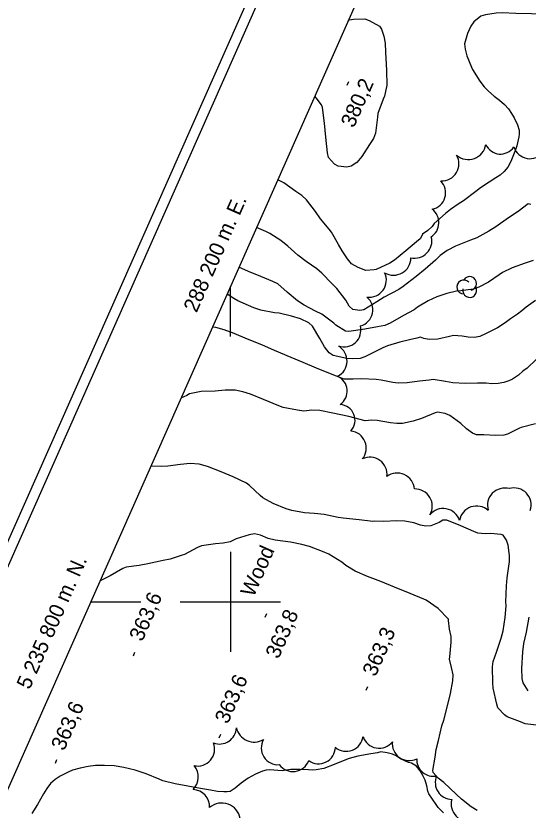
# Model space of a CAD drawing. Extents: x 287698 to 290158, y 5234163 to 5237182.
# Drawn here: x 288157.2 to 288259.4, y 5235758.4 to 5235917 of the extents above; entities that cross this region are included whole.
import ezdxf

# ---------------------------------------------------------------- set-up
doc = ezdxf.new("R2010")
doc.units = 0
for name, color, linetype in [('Niveau 1', 7, 'Continuous'), ('Niveau 2', 7, 'Continuous'), ('Niveau 3', 7, 'Continuous'), ('Niveau 44', 7, 'Continuous'), ('Niveau 60', 7, 'Continuous'), ('Niveau 61', 7, 'Continuous'), ('Niveau 7', 7, 'Continuous')]:
    doc.layers.add(name, color=color, linetype=linetype)

msp = doc.modelspace()

# ---------------------------------------------------------------- linework, layer by layer
at = {"layer": 'Niveau 1'}
for points in [[(288223.52, 5235916.11), (288223.77, 5235916.22), (288224.59, 5235916.4), (288226.82, 5235916.47), (288227.72, 5235916.09), (288229.73, 5235914.96), (288230.18, 5235914.38), (288230.63, 5235913.01), (288230.88, 5235911.6), (288230.97, 5235909.81), (288231.16, 5235906.1)], [(288231.16, 5235906.1), (288231.23, 5235903.22), (288230.74, 5235901.02), (288230.48, 5235900.41), (288229.44, 5235897.53), (288229.36, 5235896.82), (288228.98, 5235893.58), (288228.54, 5235892.53), (288227.79, 5235891.35), (288226.2, 5235888.97), (288225.23, 5235887.76), (288224.08, 5235887.02), (288223.22, 5235886.82), (288221.5, 5235887.01), (288220.79, 5235887.4), (288219.6, 5235888.78), (288219.39, 5235889.7), (288219.08, 5235892.82), (288218.77, 5235895.64), (288218.4, 5235898.72), (288218.2, 5235899.27), (288217.12, 5235900.68), (288216.82, 5235900.98)], [(288222.7, 5235844.46), (288219.98, 5235845.53), (288217.19, 5235846.69), (288214.55, 5235847.8), (288212.14, 5235848.8), (288208.83, 5235850.19), (288206.25, 5235851.3), (288203.42, 5235852.48), (288200.78, 5235853.59), (288198.77, 5235854.3), (288197.07, 5235854.77), (288196.41, 5235854.87)], [(288261.04, 5235848.38), (288259.24, 5235846.65), (288258.36, 5235846.04), (288257.48, 5235845.29), (288256.28, 5235844.47), (288255.57, 5235844.13), (288254.58, 5235843.78), (288253.44, 5235843.59), (288252.21, 5235843.56), (288251.04, 5235843.66), (288249.29, 5235843.67), (288246.86, 5235843.63), (288244.37, 5235843.75), (288242.96, 5235844), (288240.46, 5235844.42)], [(288240.46, 5235844.42), (288239.64, 5235844.24), (288237.75, 5235844.04), (288235.27, 5235843.74), (288233.5, 5235843.67), (288232.39, 5235843.78), (288230.08, 5235844.29), (288229.07, 5235844.4), (288226.11, 5235844.52), (288224.53, 5235844.46), (288222.7, 5235844.46)]]:
    msp.add_lwpolyline(points, dxfattribs=at)
at = {"layer": 'Niveau 2'}
for points in [[(288265.93, 5235917.61), (288263.29, 5235917.22), (288260.13, 5235917.46), (288256.95, 5235917.54), (288254.25, 5235917.67), (288253.07, 5235917.61), (288250.91, 5235917.27), (288250, 5235916.96), (288248.57, 5235915.85), (288247.96, 5235914.99), (288247.31, 5235913.49), (288246.75, 5235911.43), (288246.84, 5235910.36), (288247.18, 5235909.09), (288248.1, 5235906.82), (288248.35, 5235906.34)], [(288248.35, 5235906.34), (288249.8, 5235903.99), (288250.62, 5235902.86), (288251.49, 5235901.97), (288252.62, 5235901.03), (288253.71, 5235900.21), (288254.72, 5235899.35), (288255.51, 5235898.46), (288256.13, 5235897.57), (288256.65, 5235896.67), (288257.29, 5235895.27), (288257.62, 5235894.2), (288257.66, 5235893.38), (288257.57, 5235892.85), (288257.18, 5235891.11), (288256.75, 5235889.92), (288255.99, 5235887.98), (288255.38, 5235886.82), (288254.65, 5235885.94), (288253.85, 5235885.25), (288253.01, 5235884.66), (288251.66, 5235883.83), (288249.89, 5235882.66), (288248.98, 5235881.93), (288246.55, 5235880.07), (288245.45, 5235879.4), (288243.9, 5235878.37), (288242.92, 5235877.57), (288240.7, 5235875.57), (288240.26, 5235874.98), (288239.42, 5235874.19), (288238.36, 5235873.45), (288238.23, 5235873.12)], [(288238.23, 5235873.12), (288237.87, 5235872.49), (288237.16, 5235871.91), (288235, 5235870.09), (288232.76, 5235868.23), (288231.84, 5235867.65), (288229.12, 5235866.36), (288228.71, 5235866.28), (288227.01, 5235866.15), (288225.52, 5235866.75), (288224.2, 5235867.52), (288223.36, 5235868.49), (288222.29, 5235870.09), (288221.58, 5235871.37), (288220.18, 5235873.83), (288219.71, 5235874.43), (288217.95, 5235876.52), (288216.96, 5235877.94), (288215.21, 5235880.29), (288214.27, 5235881.17), (288213.08, 5235881.98), (288210.66, 5235883.69), (288209.74, 5235884.16), (288209.43, 5235884.29)], [(288259.41, 5235879.48), (288257.45, 5235877.98), (288255.53, 5235876.73), (288252.95, 5235874.89), (288251.57, 5235874.03), (288249.18, 5235872.7), (288247.9, 5235872.24), (288244.96, 5235871.01), (288243.25, 5235870.18), (288241.87, 5235869.2), (288240.92, 5235868.26), (288238.9, 5235866.46), (288237.11, 5235865.01), (288234.45, 5235862.95), (288233.59, 5235862.4), (288230.67, 5235860.83), (288229.22, 5235859.92), (288226.64, 5235858.35), (288225.86, 5235858.18), (288224.46, 5235858.41), (288223.71, 5235859.08), (288223.02, 5235860.24), (288221.25, 5235862.55), (288220.25, 5235863.57), (288218.24, 5235865.63), (288217.23, 5235866.48), (288215.11, 5235867.96), (288213.46, 5235869.27), (288211.46, 5235871.04), (288210.06, 5235872.15), (288207.85, 5235873.57), (288207.06, 5235873.96), (288205.22, 5235874.77)], [(288259.96, 5235879.35), (288259.41, 5235879.48), (288259.41, 5235879.48)], [(288260.4, 5235868.17), (288258.83, 5235867.67), (288256.23, 5235866.74), (288254.29, 5235865.81), (288253.63, 5235865.34), (288251.53, 5235863.83), (288249.59, 5235862.83), (288248.44, 5235862.45), (288245.99, 5235862.1), (288245.15, 5235862.08), (288243.2, 5235861.61), (288241.19, 5235860.94), (288239.45, 5235860.14), (288237.36, 5235858.84), (288236.7, 5235858.31), (288234.58, 5235857.18), (288231.88, 5235855.64), (288230.84, 5235855.17), (288229.35, 5235854.95), (288226.82, 5235854.45), (288223.66, 5235853.97), (288222.99, 5235854.08), (288221.02, 5235855.26), (288220.62, 5235855.64), (288218.22, 5235857.45), (288217.01, 5235858.05), (288214.73, 5235859.23), (288213.36, 5235860.14), (288211.34, 5235861.82), (288209.46, 5235863.52), (288208.5, 5235863.95), (288206.06, 5235864.96), (288203.64, 5235866.01), (288201.69, 5235866.81)], [(288237.95, 5235852.89), (288237.19, 5235852.66), (288235.75, 5235852.33), (288233.82, 5235851.86), (288231.33, 5235851.13), (288230.41, 5235850.71), (288226.81, 5235848.95), (288225.87, 5235848.63), (288224.27, 5235848.52), (288223.25, 5235848.61), (288220.51, 5235849.2), (288219.71, 5235849.72), (288218.81, 5235850.93), (288217.84, 5235852.6), (288216.38, 5235855.08), (288215.65, 5235855.7), (288213.98, 5235856.49), (288212.21, 5235857.08), (288209.74, 5235857.64), (288208.82, 5235857.74), (288206.09, 5235858.27), (288204.69, 5235858.7), (288201.45, 5235860.11), (288200.67, 5235860.57), (288199.33, 5235861.46)], [(288260.87, 5235860.17), (288259.06, 5235858.86), (288258.2, 5235858.11), (288257.32, 5235857.48), (288255.88, 5235856.54), (288254.84, 5235855.74), (288253.33, 5235854.74), (288252.22, 5235854.22), (288251.07, 5235853.57), (288249.79, 5235853), (288248.66, 5235852.81), (288247.49, 5235852.88), (288246.26, 5235853.09), (288244.54, 5235853.19), (288243.74, 5235853), (288241.37, 5235852.49), (288239.66, 5235852.38), (288238.61, 5235852.56), (288237.95, 5235852.89)], [(288226.87, 5235836.14), (288223.62, 5235837.01), (288220.47, 5235837.65), (288217.88, 5235838.2), (288216.23, 5235838.27), (288214.65, 5235838.09), (288213.36, 5235838.25), (288210.5, 5235838.8), (288209.65, 5235839.12), (288206.6, 5235840.4), (288204.04, 5235841.47), (288202.5, 5235841.96), (288200.93, 5235842.24), (288198.96, 5235842.26), (288196.97, 5235842.1), (288194.16, 5235842), (288191.86, 5235841.56), (288191.27, 5235841.21), (288190.13, 5235840.7)], [(288260.87, 5235835.55), (288258.02, 5235834.84), (288257.67, 5235834.65), (288255.33, 5235833.51), (288254.58, 5235833.3), (288252.94, 5235833.23), (288250.61, 5235833.37), (288249.09, 5235833.32), (288248.31, 5235833.68), (288247.13, 5235834.55), (288245.99, 5235835.61), (288243.79, 5235837.22), (288242.85, 5235837.64), (288241.34, 5235837.9), (288240.87, 5235837.75), (288238.16, 5235836.62), (288236.49, 5235836.11), (288234.38, 5235835.62), (288233.19, 5235835.59), (288231.93, 5235835.77), (288229.29, 5235836.22), (288228.26, 5235836.28), (288226.87, 5235836.14)], [(288228.44, 5235816.04), (288225.69, 5235816.38), (288222.49, 5235816.68), (288221.48, 5235816.86), (288218.73, 5235817.42), (288216.77, 5235817.65), (288214.76, 5235817.75), (288212.25, 5235818.21), (288211.15, 5235818.57), (288208.56, 5235819.66), (288206.49, 5235820.74), (288205.91, 5235821.2), (288203.82, 5235823.26), (288203.2, 5235823.7), (288200.52, 5235824.94), (288198.16, 5235825.93), (288195.45, 5235827.01), (288193.74, 5235827.46), (288191.94, 5235827.63), (288190.05, 5235827.42), (288187.54, 5235827.08), (288186.22, 5235827.04), (288184.1, 5235827.06)], [(288262.19, 5235775.22), (288258.85, 5235775.64), (288257.88, 5235775.99), (288255.27, 5235777.04), (288254.72, 5235777.41), (288253.39, 5235778.84), (288253.15, 5235779.52), (288252.46, 5235782.73), (288252.38, 5235783.8), (288252.34, 5235786.98), (288252.47, 5235788.1), (288253.12, 5235789.96), (288254.07, 5235792.75), (288254.44, 5235794.22), (288254.81, 5235796.89), (288255.01, 5235799.2), (288254.96, 5235800), (288255.08, 5235803.19), (288255.25, 5235804.79), (288255.71, 5235808.02), (288255.72, 5235809.26), (288255.44, 5235811.34), (288255.1, 5235812.28), (288254.43, 5235813.31), (288254.03, 5235813.47), (288251.94, 5235813.67), (288250.88, 5235813.58), (288249.36, 5235813.72), (288248.61, 5235814.04), (288245.97, 5235815.14), (288243.22, 5235816.29), (288242.37, 5235816.27), (288241.68, 5235815.84), (288240, 5235815.15), (288238.99, 5235815.1), (288237.92, 5235815.3), (288236.6, 5235815.8), (288234.83, 5235816.07), (288233.24, 5235816.14), (288230.65, 5235816.04), (288228.8, 5235816.08), (288228.44, 5235816.04)], [(288243.53, 5235796.51), (288241.49, 5235798.66), (288239.1, 5235800.29), (288238.58, 5235800.51), (288235.91, 5235801.63), (288232.77, 5235802.91), (288230.01, 5235804.04), (288227.37, 5235805.07), (288224.93, 5235806.1), (288223.01, 5235807.23), (288222.21, 5235807.92), (288219.65, 5235809.52), (288218.41, 5235810.03), (288215.81, 5235811.03), (288214.24, 5235811.46), (288211.99, 5235811.88), (288208.91, 5235812.32), (288207.51, 5235812.66), (288205.98, 5235813.28), (288204.8, 5235813.55), (288203.75, 5235813.36), (288201.18, 5235812.54), (288199.92, 5235811.99), (288198.55, 5235811.68), (288197.03, 5235811.57), (288194.22, 5235811.16), (288193.44, 5235810.83), (288190.82, 5235809.41), (288190.37, 5235809.29), (288187.96, 5235808.53), (288186.58, 5235808.27), (288183.54, 5235807.55), (288181.8, 5235807.25), (288179.22, 5235806.93), (288178.51, 5235806.67), (288175.98, 5235805.21), (288174.11, 5235804.25), (288173.98, 5235804.21)], [(288249.25, 5235758.27), (288248.03, 5235759.04), (288246.11, 5235760.55), (288245.08, 5235761.57), (288242.6, 5235763.92), (288241.44, 5235764.75), (288240.44, 5235765.88), (288240.42, 5235766.32), (288240.9, 5235768.98), (288241.06, 5235770.47), (288241.51, 5235772.3), (288242.19, 5235775.19), (288242.58, 5235776.36), (288243.33, 5235779.18), (288243.94, 5235781.67), (288244.4, 5235784.21), (288244.48, 5235785.42), (288244.12, 5235786.87), (288243.73, 5235788.53), (288243.8, 5235789), (288244.05, 5235791.91), (288244.06, 5235793.05), (288243.73, 5235794.56), (288243.54, 5235796.26), (288243.53, 5235796.51)], [(288259.46, 5235782.21), (288258.44, 5235783.79), (288258.25, 5235784.66), (288258.15, 5235786.66), (288258.34, 5235790.01), (288258.6, 5235791.69), (288259.13, 5235793.9), (288259.65, 5235796.94)]]:
    msp.add_lwpolyline(points, dxfattribs=at)
at = {"layer": 'Niveau 3'}
for p, q in [((288223.33, 5235903.22), (288223.65, 5235903.95)), ((288206.92, 5235796.92), (288207.24, 5235797.65)), ((288180.63, 5235789.22), (288180.95, 5235789.95)), ((288227.13, 5235782.36), (288227.45, 5235783.09)), ((288197.76, 5235772.85), (288198.08, 5235773.58)), ((288165.06, 5235767.75), (288165.38, 5235768.48))]:
    msp.add_line(p, q, dxfattribs=at)
at = {"layer": 'Niveau 44'}
for centre, radius, start, end in [((288247.48, 5235891.89), 3.55, 228.9928, 350.9103), ((288246.57, 5235862.88), 1.38, 44.1154, 269.804), ((288247.76, 5235863.57), 1.38, 282.2692, 149.7263), ((288247.76, 5235862.18), 1.38, 166.9369, 29.6212), ((288198.29, 5235756.09), 3.71, 9.1319, 131.0377)]:
    msp.add_arc(centre, radius, start, end, dxfattribs=at)
for centre, major_axis, ratio, start_param, end_param in [((288253.95, 5235893.11), (-0.32, -3.67), 0.911328, 5.296639, 7.272733), ((288259.84, 5235891.99), (-0.69, -3.41), 0.994237, 5.243055, 7.357987), ((288242.15, 5235887.52), (2.95, -1.79), 0.99995, 5.220249, 7.343756), ((288239.51, 5235881.73), (3.31, -0.98), 0.987893, 5.228441, 7.330417), ((288238.19, 5235875.7), (2.72, 2.09), 0.988901, 4.651024, 6.536947), ((288236.79, 5235871.99), (3.19, 1.25), 0.97886, 4.113553, 6.173926), ((288232.57, 5235868.57), (3.43, 0.06), 0.97195, 4.148607, 6.30528), ((288227.72, 5235864.19), (3.07, 1.52), 0.980687, 4.125115, 6.285844), ((288225.02, 5235858.29), (3.33, 0.84), 0.965656, 4.751088, 6.90461), ((288222.42, 5235854.56), (2.56, -2.75), 0.932855, 5.271239, 7.287702), ((288219.79, 5235848.12), (3.49, -0.15), 0.991955, 5.233385, 7.346821), ((288219.71, 5235842.06), (3.6, 0.31), 0.927978, 5.284686, 7.287978), ((288221.47, 5235836.16), (3.18, 1.29), 0.944843, 5.20176, 7.356788), ((288223.69, 5235830.71), (3.22, 1.16), 0.999336, 5.24578, 7.40579), ((288227.84, 5235825.48), (-3.42, 0.19), 0.990831, 3.0624, 5.224169), ((288233.32, 5235822.31), (-2.8, 1.98), 0.988912, 3.826522, 5.979628), ((288254.74, 5235819.37), (-3.35, -0.74), 0.973392, 4.223087, 6.380375), ((288256.57, 5235819.29), (2.85, 1.99), 0.984175, 5.360468, 7.514572), ((288236.87, 5235819.12), (3.37, 0.63), 0.995798, 5.554787, 7.710733), ((288242.5, 5235815.23), (-3.04, 1.6), 0.985648, 3.942293, 6.099271), ((288249.12, 5235815.76), (-3.23, -1.13), 0.983186, 3.632808, 5.79197), ((288197.82, 5235774.95), (2.56, 2.2), 0.999937, 3.635628, 5.538813), ((288204.74, 5235775.6), (3.62, 0.01), 0.999995, 3.348459, 5.245177), ((288209.52, 5235770.82), (-1.61, -2.96), 0.998836, 4.696279, 6.850371), ((288223.13, 5235773.5), (3.15, 1.22), 0.999856, 3.638462, 5.786316), ((288229.68, 5235774.14), (1.7, -2.92), 0.9993, 4.508409, 6.659305), ((288193.47, 5235770.56), (-0.19, 3.37), 0.999925, 2.876345, 5.029281), ((288217.58, 5235771.01), (0.62, 3.31), 0.999562, 2.71051, 4.870232), ((288235.68, 5235771.65), (2.76, -1.94), 0.999857, 3.635293, 5.789485), ((288212.47, 5235769.45), (3.34, 0.46), 0.999745, 3.635955, 5.788823), ((288240.55, 5235768.5), (2.42, -2.34), 0.999592, 3.869848, 5.663199), ((288190.12, 5235765), (1.26, 3.24), 0.999866, 4.281906, 5.790847), ((288244.27, 5235763.89), (1.54, -3.01), 0.999856, 3.84473, 5.787041), ((288192.38, 5235759.03), (-2.99, 1.76), 0.999985, 3.632266, 5.197746), ((288247.43, 5235759.57), (2.41, -2.36), 0.999746, 3.634735, 5.790043)]:
    msp.add_ellipse(centre, major_axis=major_axis, ratio=ratio, start_param=start_param, end_param=end_param, dxfattribs=at)
at = {"layer": 'Niveau 60'}
for points in [[(289088.15, 5234163.34), (287698.12, 5234778.71), (288762.01, 5237181.96), (290152.07, 5236566.6), (289088.15, 5234163.34)], [(289087.13, 5234165.98), (287700.76, 5234779.73), (288763.06, 5237179.33), (290149.43, 5236565.58), (289087.13, 5234165.98)]]:
    msp.add_lwpolyline(points, dxfattribs=at)
msp.add_lwpolyline([(289077.96, 5234189.73), (287724.51, 5234788.9), (288562.53, 5236681.9), (289915.99, 5236082.74)], close=True, dxfattribs=at)
at = {"layer": 'Niveau 61'}
for p, q in [((288200, 5235852.98), (288200, 5235862.98)), ((288172.12, 5235800), (288182.12, 5235800))]:
    msp.add_line(p, q, dxfattribs=at)
for points in [[(288200, 5235810), (288200, 5235800), (288200, 5235790)], [(288190, 5235800), (288200, 5235800), (288210, 5235800)]]:
    msp.add_lwpolyline(points, dxfattribs=at)
at = {"layer": 'Niveau 7'}
msp.add_lwpolyline([(288242.52, 5235757.86), (288241.48, 5235758.9), (288241.07, 5235759.48), (288239.59, 5235761.63), (288239.4, 5235762.14), (288239.2, 5235763.24), (288238.86, 5235764.34), (288238.43, 5235765.32), (288237.89, 5235766.25), (288237.12, 5235767.16), (288236.16, 5235767.73), (288235.57, 5235767.91), (288233.92, 5235768.62), (288233.07, 5235769.22), (288232.35, 5235769.54), (288231.26, 5235769.83), (288230.02, 5235769.99), (288229.33, 5235769.81), (288228.02, 5235769.59), (288225.45, 5235769.14), (288223.72, 5235768.67), (288222.15, 5235768.09), (288220.7, 5235767.48), (288218.65, 5235766.72), (288217.13, 5235766.41), (288216.38, 5235766.37), (288215.6, 5235766.44), (288213.91, 5235766.52), (288212.04, 5235766.47), (288210.32, 5235766.26), (288209.47, 5235766.28), (288207.89, 5235766.41), (288207.14, 5235766.36), (288206.42, 5235766.17), (288204.98, 5235765.55), (288203.52, 5235764.74), (288202.17, 5235763.78), (288200.95, 5235762.79), (288199.98, 5235762.13), (288199.34, 5235762.01), (288198.71, 5235762.02), (288197.45, 5235762.11), (288196.03, 5235762.36), (288194, 5235762.71), (288191.48, 5235763.16), (288188.95, 5235763.6), (288186.54, 5235764.21), (288185.78, 5235764.54), (288183.19, 5235765.65), (288181.01, 5235766.37), (288178.72, 5235766.92), (288176.79, 5235767.23), (288174.86, 5235767.3), (288173.07, 5235767.28), (288171.6, 5235767.1), (288170.04, 5235766.77), (288168.46, 5235766.35), (288167.74, 5235766.05), (288166.01, 5235765.16), (288165.04, 5235764.5), (288164.1, 5235763.67), (288163.33, 5235762.69), (288162.68, 5235761.63), (288161.48, 5235759.51), (288160.39, 5235757.69)], dxfattribs=at)

# ---------------------------------------------------------------- texts
at = {"layer": 'Niveau 3'}
for s, p in [('380,2', (288224.63, 5235894.51)), ('363,6', (288182.4, 5235791.9)), ('363,8', (288209.6, 5235788.44)), ('363,3', (288228.96, 5235784.88)), ('363,6', (288199.48, 5235775.43)), ('363,6', (288166.8, 5235770.07))]:
    msp.add_text(s, height=3, rotation=66.1217, dxfattribs=at).set_placement(p)
at = {"layer": 'Niveau 44'}
msp.add_text('Wood', height=3, rotation=66.1212, dxfattribs=at).set_placement((288204.63, 5235800.77))
at = {"layer": 'Niveau 61'}
for s, p in [('288 200 m. E.', (288193.24, 5235857.6)), ('5 235 800 m. N.', (288159.92, 5235782.32))]:
    msp.add_text(s, height=3, rotation=66.1213, dxfattribs=at).set_placement(p)

doc.saveas('drawing.dxf')
